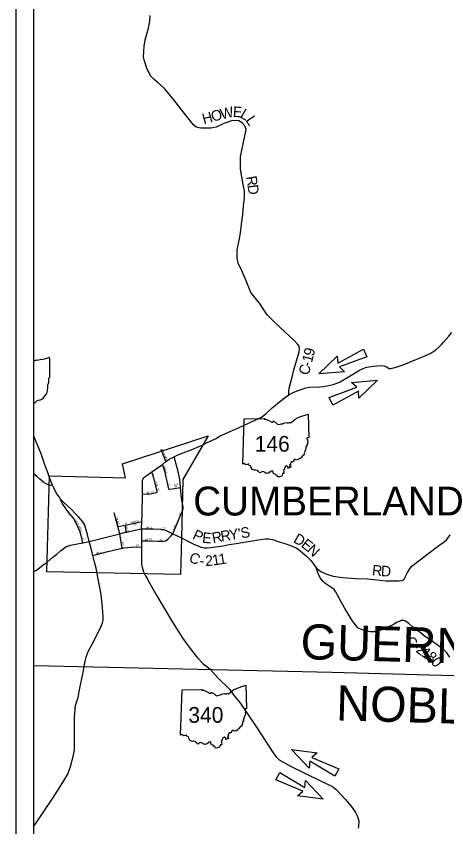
# Model space of a CAD drawing. Extents: x 0 to 34, y 0 to 22.
# Drawn here: x 19.758 to 22.078, y 13.537 to 17.905 of the extents above; entities that cross this region are included whole.
import ezdxf

# ---------------------------------------------------------------- set-up
doc = ezdxf.new("R2010")
doc.units = 0
for name, color, linetype in [('Default', 7, 'Continuous'), ('GM_X_City_Street', 7, 'Continuous'), ('GM_X_City_Street_Text', 7, 'Continuous'), ('GM_X_Corporation', 7, 'Continuous'), ('GM_X_County_Road_Text', 7, 'Continuous'), ('GM_X_State_Route', 7, 'Continuous'), ('GM_X_State_Shield', 7, 'Continuous'), ('GM_X_Township', 7, 'Continuous'), ('GM_X_Township_Road', 7, 'Continuous'), ('GM_X_Unincorporated_Text', 7, 'Continuous')]:
    doc.layers.add(name, color=color, linetype=linetype)

msp = doc.modelspace()

# ---------------------------------------------------------------- linework, layer by layer
at = {"layer": 'Default'}
for p, q in [((19.8526, 9.6182), (19.8526, 20.4625)), ((21.388, 15.9771), (21.4878, 16.0738)), ((21.4878, 16.0738), (21.49, 16.0357)), ((21.49, 16.0357), (21.6287, 16.1107)), ((21.6287, 16.1107), (21.647, 16.0699)), ((21.647, 16.0699), (21.4993, 16.0152)), ((21.5266, 15.9883), (21.388, 15.9771)), ((21.4993, 16.0152), (21.5266, 15.9883)), ((21.565, 15.9319), (21.7035, 15.9432)), ((21.7035, 15.9432), (21.6036, 15.8465)), ((21.4444, 15.8505), (21.5922, 15.9052)), ((21.5922, 15.9052), (21.565, 15.9319)), ((21.6015, 15.8845), (21.4629, 15.8096)), ((21.6036, 15.8465), (21.6015, 15.8845)), ((21.4629, 15.8096), (21.4444, 15.8505)), ((20.9787, 15.4917), (20.9866, 15.7358)), ((20.6438, 14.0311), (20.6516, 14.2751)), ((21.2408, 13.9535), (21.3787, 13.9363)), ((21.3363, 13.8525), (21.2408, 13.9535)), ((21.3787, 13.9363), (21.3504, 13.9107)), ((21.3402, 13.8907), (21.3363, 13.8525)), ((21.4754, 13.8098), (21.3402, 13.8907)), ((21.3504, 13.9107), (21.4957, 13.8496)), ((21.4957, 13.8496), (21.4754, 13.8098)), ((21.1572, 13.7903), (21.1774, 13.8303)), ((21.1774, 13.8303), (21.3127, 13.7493)), ((21.3023, 13.7291), (21.1572, 13.7903)), ((21.3127, 13.7493), (21.3165, 13.7873)), ((21.3165, 13.7873), (21.412, 13.6864)), ((21.2741, 13.7036), (21.3023, 13.7291)), ((21.412, 13.6864), (21.2741, 13.7036))]:
    msp.add_line(p, q, dxfattribs=at)
msp.add_lwpolyline([(19.7581, 20.557), (30.7915, 20.557), (30.7915, 9.5237), (19.7581, 9.5237)], close=True, dxfattribs=at)
for points in [[(21.2267, 15.8642), (21.2267, 15.8817), (21.2292, 15.9013), (21.2441, 15.9597), (21.2545, 15.9989), (21.2817, 16.097), (21.2837, 16.1152), (21.2824, 16.1263), (21.2761, 16.1366), (21.2559, 16.158), (21.1795, 16.228), (21.1297, 16.2763), (21.1105, 16.2961), (21.0959, 16.3166), (21.0742, 16.3511), (21.0215, 16.416), (20.996, 16.4782), (20.9693, 16.5409), (20.9542, 16.5717), (20.9485, 16.6035), (20.9486, 16.6451), (20.9614, 16.7066), (20.9667, 16.7368), (20.9722, 16.7844), (20.9788, 16.8365), (20.9824, 16.8826), (20.9886, 16.9252), (20.9875, 16.9612), (20.9804, 16.9983), (20.9666, 17.0798), (20.9663, 17.1119), (20.9671, 17.1463), (20.9715, 17.1739), (20.9971, 17.2946), (20.9894, 17.314), (20.9757, 17.33), (20.9577, 17.3401), (20.923, 17.342), (20.8768, 17.3267), (20.8358, 17.3064), (20.8063, 17.3022), (20.7519, 17.3006), (20.7271, 17.3062), (20.7133, 17.3189), (20.6571, 17.3887), (20.6068, 17.4535), (20.5984, 17.4643), (20.5568, 17.5148), (20.5232, 17.5458), (20.5011, 17.5635), (20.4817, 17.5834), (20.4611, 17.6241), (20.4491, 17.6628), (20.4445, 17.6852), (20.447, 17.7426), (20.4535, 17.7777), (20.4705, 17.8407), (20.4777, 17.878), (20.4804, 17.909)], [(22.0485, 16.1355), (22.062, 16.1504), (22.0887, 16.1812), (22.104, 16.2014)], [(21.5028, 15.9341), (21.5573, 15.9673), (21.6069, 15.9972), (21.6403, 16.0124), (21.6475, 16.0143), (21.6819, 16.0188), (21.7236, 16.0226), (21.7406, 16.0215), (21.7531, 16.0154), (21.7671, 16.0067), (21.7759, 16.0063), (21.7978, 16.0116), (21.8107, 16.015), (21.8418, 16.026), (21.9075, 16.0527), (21.9345, 16.0643), (21.9688, 16.0783), (21.9908, 16.089), (22.0182, 16.1075), (22.0369, 16.1227), (22.0485, 16.1355)], [(20.7838, 15.6054), (20.8345, 15.6294), (20.8532, 15.6412), (20.9147, 15.6691), (20.9789, 15.6981), (21.0264, 15.7184), (21.0652, 15.7368), (21.0796, 15.7442), (21.1045, 15.7643), (21.1376, 15.7945), (21.1946, 15.8419), (21.2081, 15.8513), (21.2267, 15.8642), (21.2464, 15.8754), (21.2708, 15.8871), (21.2983, 15.8959), (21.3178, 15.9022), (21.3374, 15.9056), (21.3919, 15.9077), (21.4123, 15.9094), (21.4335, 15.9123), (21.4654, 15.9198), (21.4911, 15.9296), (21.5012, 15.9331), (21.5028, 15.9341)], [(20.9866, 15.7358), (21.0948, 15.7373), (21.0931, 15.7344), (21.1033, 15.7338), (21.1141, 15.7285), (21.1233, 15.7253), (21.1345, 15.7175), (21.1412, 15.7176), (21.1441, 15.724), (21.1492, 15.719), (21.1553, 15.7182), (21.1659, 15.7065), (21.1746, 15.704), (21.185, 15.708), (21.1928, 15.7086), (21.1985, 15.7126), (21.2133, 15.716), (21.2175, 15.7139), (21.2254, 15.7144), (21.2293, 15.7158), (21.2362, 15.7145), (21.2482, 15.7234), (21.2606, 15.7338), (21.2798, 15.7437), (21.3083, 15.753), (21.3309, 15.7614), (21.3341, 15.6348)], [(20.4466, 15.4191), (20.4529, 15.4242), (20.4748, 15.4397), (20.4893, 15.4492), (20.5457, 15.4898), (20.5635, 15.5054), (20.5823, 15.518), (20.6099, 15.5311), (20.6292, 15.5407), (20.7006, 15.5687), (20.7641, 15.596), (20.7838, 15.6054)], [(21.3341, 15.6348), (21.3308, 15.633), (21.3256, 15.6338), (21.3222, 15.6303), (21.3265, 15.6244), (21.3285, 15.6181), (21.3267, 15.6112), (21.3285, 15.6055), (21.3273, 15.6008), (21.324, 15.596), (21.3229, 15.5915), (21.3201, 15.5867), (21.3203, 15.5841), (21.3177, 15.582), (21.3182, 15.574), (21.3168, 15.5697), (21.3173, 15.5659), (21.313, 15.5649), (21.314, 15.5618), (21.3112, 15.5593), (21.3118, 15.5552), (21.3087, 15.5525), (21.3117, 15.5472), (21.3093, 15.5455), (21.3073, 15.5391), (21.3018, 15.5377), (21.2909, 15.526), (21.287, 15.5215), (21.2826, 15.5204), (21.2802, 15.5158), (21.2749, 15.5158), (21.2667, 15.5126), (21.2614, 15.518), (21.2522, 15.5115), (21.2512, 15.5038), (21.2396, 15.5041), (21.24, 15.5002), (21.2374, 15.4991), (21.2351, 15.4953), (21.2364, 15.4884), (21.2309, 15.4867), (21.2316, 15.4827), (21.2351, 15.4803), (21.2367, 15.4727), (21.2309, 15.4742), (21.2262, 15.4678), (21.2212, 15.4693), (21.2228, 15.4747), (21.2146, 15.4813), (21.2068, 15.4761), (21.2027, 15.4677), (21.2027, 15.462), (21.1968, 15.4587), (21.2006, 15.4508), (21.1999, 15.4453), (21.2, 15.44), (21.1928, 15.4403), (21.1883, 15.4262)], [(21.1883, 15.4262), (21.1757, 15.4236), (21.167, 15.422), (21.1639, 15.4283), (21.1576, 15.4317), (21.1535, 15.4381), (21.1445, 15.4389), (21.1424, 15.4478), (21.1414, 15.4549), (21.1291, 15.4531), (21.1258, 15.4488), (21.1214, 15.4476), (21.1188, 15.4432), (21.1129, 15.4428), (21.1065, 15.4407), (21.1023, 15.445), (21.0918, 15.4494), (21.0871, 15.4516), (21.0773, 15.4482), (21.0752, 15.4441), (21.0674, 15.4459), (21.0656, 15.4505), (21.0608, 15.4519), (21.0598, 15.4567), (21.0497, 15.4593), (21.0419, 15.4583), (21.0282, 15.4622), (21.0274, 15.4686), (21.0227, 15.4764), (21.0204, 15.4818), (21.0117, 15.4859), (21.0099, 15.4923), (21.0072, 15.4921), (21.0047, 15.4895), (20.995, 15.4883), (20.9912, 15.4909), (20.9859, 15.4955), (20.9787, 15.4917)], [(20.4339, 15.1432), (20.4351, 15.1817), (20.4365, 15.2193), (20.4389, 15.3318), (20.4388, 15.4004), (20.44, 15.4079), (20.4414, 15.4125), (20.4452, 15.4179), (20.4466, 15.4191)], [(20.4339, 15.1432), (20.4339, 15.0785), (20.4333, 15.046), (20.4328, 15.0197), (20.4331, 15.0013)], [(20.6479, 15.0937), (20.6896, 15.0728), (20.7119, 15.0624), (20.7448, 15.0475), (20.7518, 15.0444), (20.7629, 15.0413), (20.7733, 15.0402), (20.787, 15.0404), (20.8043, 15.0422), (20.8726, 15.052), (20.9062, 15.0579), (20.9432, 15.0637), (21.0183, 15.0759), (21.0739, 15.0859), (21.1012, 15.0891), (21.1165, 15.0891), (21.1389, 15.0847), (21.1794, 15.0717), (21.2051, 15.0637), (21.227, 15.0566), (21.2485, 15.0478), (21.266, 15.0398), (21.279, 15.0305), (21.297, 15.0166), (21.3208, 14.997), (21.3449, 14.9716), (21.3623, 14.9504), (21.3761, 14.9313)], [(21.3761, 14.9313), (21.3893, 14.9205), (21.3996, 14.9122), (21.4109, 14.9071), (21.4312, 14.898), (21.4469, 14.8925), (21.4658, 14.8878), (21.4902, 14.8842), (21.5169, 14.8808), (21.5841, 14.8757), (21.649, 14.8732), (21.7514, 14.8633), (21.8189, 14.8617), (21.8375, 14.8645), (21.8474, 14.8716), (21.8663, 14.9073), (21.8778, 14.9279), (21.8916, 14.9436), (21.9286, 14.9723), (21.9834, 15.014), (22.02, 15.043), (22.0397, 15.056), (22.0637, 15.0731), (22.0771, 15.0851), (22.0962, 15.1109)], [(20.4331, 15.0013), (20.4331, 14.9943), (20.4322, 14.9613), (20.4322, 14.9507), (20.4362, 14.9364), (20.4433, 14.9117)], [(20.4433, 14.9117), (20.4434, 14.9111), (20.452, 14.8934), (20.465, 14.8708), (20.48, 14.8452), (20.5164, 14.7823), (20.5504, 14.7242), (20.5996, 14.6395), (20.6337, 14.5856), (20.6526, 14.5567), (20.6705, 14.5312), (20.7008, 14.4905), (20.7349, 14.4476), (20.7653, 14.4162), (20.8016, 14.3885)], [(22.0938, 14.4507), (22.0776, 14.4746), (22.0597, 14.4925), (22.0461, 14.5035), (22.0253, 14.5175), (21.9947, 14.5388), (21.9565, 14.5664), (21.9421, 14.5787), (21.9212, 14.5927), (21.8932, 14.6148), (21.8727, 14.6324), (21.861, 14.6411), (21.8515, 14.647), (21.8443, 14.6497), (21.8387, 14.6497), (21.8327, 14.6482), (21.8214, 14.6438), (21.8086, 14.6372), (21.7904, 14.628), (21.7594, 14.6125), (21.7281, 14.5985), (21.7083, 14.5911), (21.6967, 14.5881), (21.6833, 14.5871), (21.665, 14.5881), (21.6456, 14.5923), (21.6231, 14.5985), (21.6095, 14.6037), (21.5993, 14.6102), (21.5909, 14.6174), (21.5832, 14.6275), (21.5649, 14.6535), (21.5456, 14.6845), (21.5279, 14.7138), (21.4987, 14.7696), (21.4787, 14.8057), (21.4703, 14.8159), (21.4624, 14.8227), (21.4394, 14.8368), (21.419, 14.8519), (21.4113, 14.8591), (21.4007, 14.8723), (21.392, 14.8864), (21.3856, 14.9023), (21.378, 14.9211), (21.3761, 14.9313)], [(20.8016, 14.3885), (20.8447, 14.3395), (20.9077, 14.279), (20.9274, 14.2505), (20.9619, 14.2076), (21.0482, 14.0796), (21.1464, 13.9313), (21.1582, 13.9137), (21.1739, 13.8984), (21.2388, 13.863), (21.3981, 13.7855), (21.4619, 13.7536), (21.4814, 13.7382), (21.5321, 13.6841), (21.5678, 13.6416), (21.5859, 13.6152), (21.5958, 13.5935), (21.6045, 13.5672), (21.6018, 13.5388), (21.601, 13.5305)], [(20.6516, 14.2751), (20.7598, 14.2767), (20.7582, 14.2737), (20.7683, 14.2732), (20.7792, 14.2679), (20.7884, 14.2647), (20.7995, 14.2569), (20.8062, 14.257), (20.8091, 14.2634), (20.8142, 14.2584), (20.8204, 14.2576), (20.8309, 14.2459), (20.8396, 14.2434), (20.8501, 14.2474), (20.8578, 14.248), (20.8635, 14.252), (20.8784, 14.2553), (20.8826, 14.2533), (20.8904, 14.2538), (20.8944, 14.2552), (20.9013, 14.2539), (20.9132, 14.2628), (20.9257, 14.2732), (20.9448, 14.2831), (20.9733, 14.2924), (20.9959, 14.3008), (20.9992, 14.1741)], [(20.9992, 14.1741), (20.9959, 14.1724), (20.9907, 14.1732), (20.9872, 14.1697), (20.9915, 14.1638), (20.9935, 14.1575), (20.9917, 14.1506), (20.9935, 14.1449), (20.9923, 14.1401), (20.9891, 14.1354), (20.9879, 14.1309), (20.9851, 14.1261), (20.9853, 14.1234), (20.9827, 14.1214), (20.9832, 14.1134), (20.9819, 14.1091), (20.9823, 14.1053), (20.978, 14.1043), (20.979, 14.1011), (20.9763, 14.0987), (20.9769, 14.0946), (20.9738, 14.0919), (20.9768, 14.0866), (20.9744, 14.0849), (20.9724, 14.0784), (20.9668, 14.0771), (20.9559, 14.0653), (20.952, 14.0609), (20.9477, 14.0597), (20.9452, 14.0552), (20.9399, 14.0552), (20.9317, 14.0519), (20.9265, 14.0574), (20.9173, 14.0508), (20.9162, 14.0432), (20.9046, 14.0435), (20.905, 14.0396), (20.9024, 14.0385), (20.9001, 14.0347), (20.9015, 14.0278), (20.896, 14.026), (20.8967, 14.0221), (20.9002, 14.0197), (20.9017, 14.0121), (20.8959, 14.0136), (20.8912, 14.0072), (20.8863, 14.0087), (20.8879, 14.0141), (20.8796, 14.0207), (20.8718, 14.0155), (20.8678, 14.0071), (20.8677, 14.0014), (20.8619, 13.998), (20.8657, 13.9901), (20.8649, 13.9847), (20.8651, 13.9794), (20.8578, 13.9796), (20.8534, 13.9656)], [(20.8534, 13.9656), (20.8408, 13.9629), (20.8321, 13.9614), (20.8289, 13.9677), (20.8227, 13.9711), (20.8186, 13.9774), (20.8096, 13.9783), (20.8074, 13.9872), (20.8064, 13.9943), (20.7941, 13.9925), (20.7908, 13.9881), (20.7864, 13.987), (20.7839, 13.9826), (20.7779, 13.9822), (20.7715, 13.9801), (20.7673, 13.9844), (20.7569, 13.9888), (20.7522, 13.991), (20.7423, 13.9876), (20.7403, 13.9834), (20.7325, 13.9852), (20.7306, 13.9898), (20.7259, 13.9912), (20.7248, 13.9961), (20.7147, 13.9987), (20.7069, 13.9976), (20.6933, 14.0015), (20.6924, 14.0079), (20.6878, 14.0157), (20.6854, 14.0212), (20.6768, 14.0252), (20.675, 14.0317), (20.6723, 14.0315), (20.6697, 14.0289), (20.6601, 14.0277), (20.6563, 14.0303), (20.6509, 14.0348), (20.6438, 14.0311)]]:
    msp.add_lwpolyline(points, dxfattribs=at)
at = {"layer": 'GM_X_City_Street'}
for points in [[(20.5635, 15.5054), (20.5383, 15.5696)], [(20.6019, 15.1156), (20.6512, 15.2321), (20.6572, 15.2503), (20.6572, 15.2616), (20.6481, 15.3087), (20.6435, 15.3656), (20.64, 15.4087), (20.6317, 15.4443), (20.6099, 15.5311)], [(20.5796, 15.3556), (20.5682, 15.4135), (20.5597, 15.4465), (20.5457, 15.4898)], [(20.5154, 15.3383), (20.5182, 15.342), (20.518, 15.3456), (20.5122, 15.366), (20.5009, 15.4095), (20.4964, 15.4262), (20.4956, 15.4342), (20.4932, 15.4396), (20.4893, 15.4492)], [(19.9544, 15.3772), (19.9475, 15.3762), (19.9382, 15.3776), (19.9314, 15.3792), (19.9258, 15.3822)], [(20.4389, 15.3318), (20.4713, 15.3297), (20.5154, 15.3383)], [(20.5796, 15.3556), (20.5857, 15.3563), (20.6114, 15.3606), (20.6435, 15.3656)], [(20.1075, 15.1074), (20.1007, 15.1309), (20.0918, 15.1505), (20.0796, 15.1765), (20.0665, 15.1994), (20.0438, 15.2266), (20.0289, 15.2477), (20.0054, 15.2802), (19.9977, 15.2949), (19.9976, 15.3034)], [(20.3161, 15.1159), (20.3057, 15.1549), (20.2857, 15.2295)], [(20.3057, 15.1549), (20.3445, 15.163), (20.4351, 15.1817)], [(20.352, 15.1254), (20.3445, 15.163)], [(20.3297, 15.0387), (20.3163, 15.1153), (20.3161, 15.1159)], [(20.4339, 15.1432), (20.4676, 15.1427), (20.4957, 15.1422), (20.5379, 15.1401)], [(20.5205, 15.077), (20.5219, 15.077), (20.5496, 15.0767), (20.5624, 15.0787), (20.5745, 15.0868), (20.5918, 15.104), (20.6019, 15.1156)], [(20.5379, 15.1401), (20.5403, 15.14), (20.5519, 15.1394), (20.563, 15.1349), (20.6019, 15.1156)], [(20.6019, 15.1156), (20.6479, 15.0937)], [(20.1172, 15.0672), (20.1079, 15.1061), (20.1075, 15.1074)], [(20.4339, 15.0785), (20.4655, 15.078), (20.5205, 15.077)], [(20.1711, 14.9995), (20.2443, 15.019), (20.3297, 15.0387), (20.3321, 15.0389), (20.3381, 15.0396)], [(20.3381, 15.0396), (20.3781, 15.0441), (20.4333, 15.046)]]:
    msp.add_lwpolyline(points, dxfattribs=at)
at = {"layer": 'GM_X_Corporation'}
msp.add_lwpolyline([(20.3303, 15.4922), (20.7918, 15.6442), (20.6561, 15.4092), (20.6478, 15.0912), (20.6428, 14.8958), (19.9223, 14.9103), (19.9368, 15.4289), (20.3468, 15.4175)], close=True, dxfattribs=at)
at = {"layer": 'GM_X_State_Route'}
for points in [[(19.9358, 15.4235), (19.9277, 15.4471), (19.9142, 15.4816), (19.8933, 15.546), (19.8526, 15.6428)], [(20.1506, 15.075), (20.1506, 15.075), (20.1419, 15.1118), (20.128, 15.1618), (20.1162, 15.1806), (20.0954, 15.2054), (20.0802, 15.2212), (20.0516, 15.2501), (20.0152, 15.2853), (19.9976, 15.3034), (19.989, 15.3149), (19.9775, 15.3305), (19.9686, 15.347), (19.9594, 15.3665), (19.9544, 15.3772), (19.9362, 15.4223), (19.9358, 15.4235)], [(20.1506, 15.075), (20.3163, 15.1153), (20.3469, 15.1242), (20.352, 15.1254), (20.3736, 15.1308), (20.4339, 15.1432)], [(19.999, 15.0264), (20.0104, 15.0355), (20.0193, 15.0421), (20.0296, 15.0476), (20.0511, 15.0541), (20.1172, 15.0672), (20.1506, 15.075)], [(20.1918, 14.9121), (20.188, 14.9305), (20.1787, 14.9704), (20.1711, 14.9995), (20.1613, 15.0373), (20.1506, 15.075)], [(19.8526, 14.9121), (19.8669, 14.9208), (19.902, 14.947), (19.924, 14.9628), (19.9563, 14.99), (19.9769, 15.0069), (19.9959, 15.0239), (19.999, 15.0264)], [(20.1238, 14.403), (20.1315, 14.4368), (20.1349, 14.4519), (20.1406, 14.468), (20.15, 14.4887), (20.1654, 14.5177), (20.1919, 14.5692), (20.2159, 14.6177), (20.223, 14.6366), (20.2267, 14.6502), (20.2272, 14.6686), (20.2235, 14.717), (20.217, 14.7723), (20.2115, 14.8084), (20.1984, 14.8801), (20.1918, 14.9121)], [(19.8526, 13.5389), (19.8544, 13.5419), (19.955, 13.6924), (20.0146, 13.7843), (20.0367, 13.82), (20.0513, 13.863), (20.0673, 13.9226), (20.0719, 13.9528), (20.0722, 14.0297), (20.0721, 14.1281), (20.0783, 14.1917), (20.0918, 14.2344), (20.0999, 14.2747), (20.119, 14.3696), (20.1238, 14.403)]]:
    msp.add_lwpolyline(points, dxfattribs=at)
at = {"layer": 'GM_X_State_Shield'}
for p, q in [((19.9368, 16.0625), (19.9368, 15.958)), ((19.9368, 15.958), (19.9367, 15.9581))]:
    msp.add_line(p, q, dxfattribs=at)
for centre, radius, start, end in [((19.8786, 15.9966), 0.0561, 97.3462, 117.5636), ((19.843, 16.3298), 0.279, 275.8445, 288.9065), ((19.9338, 16.0629), 0.00293, 351.8621, 97.738), ((19.9361, 15.9504), 0.00453, 107.944, 210.337), ((19.9072, 15.9372), 0.0272, 340.033, 23.6496), ((19.9336, 15.9576), 0.00313, 289.6038, 7.7341), ((19.8587, 15.901), 0.0698, 292.3089, 8.9858), ((19.9472, 15.9143), 0.0198, 136.8065, 186.9296), ((19.8397, 15.8351), 0.0225, 305.1621, 323.2771), ((19.8881, 15.7983), 0.0382, 94.4031, 142.5768)]:
    msp.add_arc(centre, radius, start, end, dxfattribs=at)
at = {"layer": 'GM_X_Township'}
for p, q in [((19.8526, 14.4071), (21.4596, 14.3709)), ((21.4596, 14.3709), (23.5089, 14.3112))]:
    msp.add_line(p, q, dxfattribs=at)
at = {"layer": 'GM_X_Township_Road'}
msp.add_lwpolyline([(19.9258, 15.3822), (19.9196, 15.3853), (19.9071, 15.3929), (19.8855, 15.4103), (19.8686, 15.424), (19.8591, 15.4328), (19.8546, 15.4399), (19.8526, 15.4455)], dxfattribs=at)

# ---------------------------------------------------------------- texts
at = {"layer": 'Default'}
for s, p in [('146', (21.043, 15.5586)), ('340', (20.6855, 14.098))]:
    msp.add_text(s, height=0.08462, dxfattribs=at).set_placement(p)
at = {"layer": 'GM_X_City_Street_Text'}
for s, rotation, p in [('SINGER', 293.4993, (20.5395, 15.57)), ('RD', 293.9614, (20.557, 15.5293)), ('MAPLE', 287.2778, (20.5512, 15.4792)), ('ELM', 285.9444, (20.5055, 15.3985)), ('ST', 284.9242, (20.5753, 15.3877)), ('1ST', 9.8702, (20.608, 15.3731)), ('ST', 7.12, (20.6118, 15.3629)), ('1', 354.7773, (20.4593, 15.3332)), ('S', 357.0818, (20.4655, 15.3326)), ('T', 11.9171, (20.4748, 15.3325)), ('ST', 10.6213, (20.4861, 15.3348)), ('ST', 288.4262, (20.5163, 15.3603)), ('BROAD', 285.4621, (20.2934, 15.2089)), ('ST', 66.8023, (20.6412, 15.2133)), ('CEMETERY', 295.8879, (20.0746, 15.1901)), ('BANK ST', 280.7367, (20.3442, 15.1755)), ('NORTH', 12.0102, (20.3755, 15.171)), ('ST', 11.3113, (20.392, 15.1585)), ('CARL', 68.1986, (20.6088, 15.1342)), ('MAIN', 358.4498, (20.4557, 15.1452)), ('S', 352.3259, (20.5448, 15.1419)), ('T', 346.8784, (20.5511, 15.1411)), ('ST', 284.9242, (20.1121, 15.0966)), ('ST', 280.6135, (20.3267, 15.0715)), ('W', 357.1242, (20.4508, 15.0804)), ('A', 358.3602, (20.4618, 15.0798)), ('T', 359.7134, (20.4704, 15.0796)), ('E', 359.9956, (20.4771, 15.0796)), ('R', 359.9941, (20.4837, 15.0796)), ('ST', 0, (20.5305, 15.0787)), ('ST', 3.5738, (20.4032, 15.0471)), ('MILL', 13.6288, (20.1883, 15.0063))]:
    msp.add_text(s, height=0.00945, rotation=rotation, dxfattribs=at).set_placement(p)
at = {"layer": 'GM_X_County_Road_Text'}
for s, rotation, p in [('H', 15.3104, (20.7685, 17.3224)), ('O', 15.3077, (20.8166, 17.3356)), ('W', 12.7639, (20.8641, 17.3486)), ('E', 355.8094, (20.9237, 17.3628)), ('L', 329.3626, (20.9595, 17.3617)), ('L', 304.0051, (20.9912, 17.3447)), ('R', 280.0706, (20.9958, 17.0393)), ('D', 277.1474, (21.0039, 16.9942)), ('9', 76.11, (21.3599, 16.0693)), ('1', 75.274, (21.3508, 16.0346)), ('-', 75.1213, (21.3448, 16.0119)), ('C', 75.0749, (21.3328, 15.9669)), ('P', 334.8716, (20.7035, 15.0904)), ('E', 353.6707, (20.7576, 15.0687)), ('R', 11.1712, (20.8186, 15.0648)), ('R', 9.2551, (20.8638, 15.0737)), ('Y', 9.2545, (20.9097, 15.0812)), ("'", 9.2581, (20.959, 15.0892)), ('S', 9.253, (20.9713, 15.0912)), ('D', 330.927, (21.2469, 15.0723)), ('E', 322.0664, (21.2886, 15.0494)), ('N', 316.6629, (21.3209, 15.0242)), ('C', 336.9769, (20.6838, 14.9677)), ('2', 3.5213, (20.7778, 14.942)), ('1', 8.7072, (20.8182, 14.9447)), ('1', 8.7566, (20.8528, 14.95)), ('-', 353.4185, (20.7438, 14.9449)), ('R', 354.1745, (21.6729, 14.8931)), ('D', 356.2646, (21.7214, 14.8882)), ('C', 322.2387, (21.8494, 14.5255)), ('-', 324.3443, (21.888, 14.4956)), ('2', 324.3596, (21.9069, 14.482)), ('1', 324.3438, (21.9353, 14.4617)), ('8', 323.841, (21.9636, 14.4414)), ('0', 309.7026, (21.9891, 14.4233))]:
    msp.add_text(s, height=0.0567, rotation=rotation, dxfattribs=at).set_placement(p)
at = {"layer": 'GM_X_Unincorporated_Text'}
for s, height, rotation, p in [('CUMBERLAND', 0.15568, 0, (20.7118, 15.2147)), ('GUERNSEY COUNTY', 0.189, 358.4232, (21.2882, 14.4412)), ('NOBLE COUNTY', 0.189, 358.4232, (21.4801, 14.1108))]:
    msp.add_text(s, height=height, rotation=rotation, dxfattribs=at).set_placement(p)

doc.saveas('drawing.dxf')
